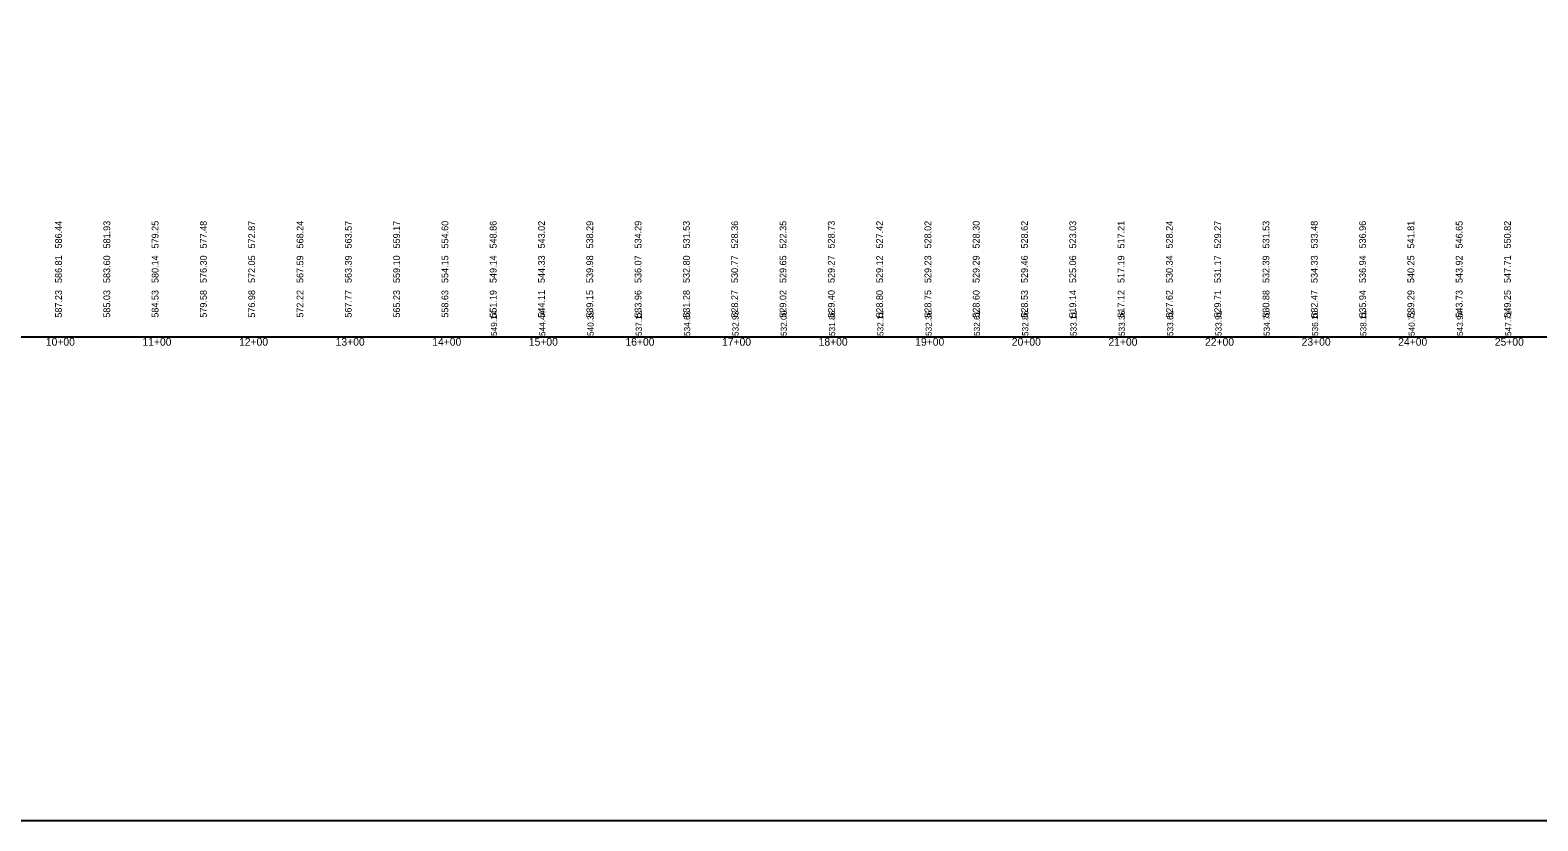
# Model space of a CAD drawing. Extents: x 1511486 to 1516886, y 901686 to 906985.
# Drawn here: x 1513041 to 1514602, y 903685 to 904504 of the extents above; entities that cross this region are included whole.
import ezdxf

# ---------------------------------------------------------------- set-up
doc = ezdxf.new("R2010")
doc.units = 0
for name, color, linetype in [('RD_DDB_StaTX', 7, 'Continuous'), ('RD_DDB_StripGrade', 7, 'Continuous'), ('RD_GPK_Profile_Cell', 7, 'Continuous'), ('RD_Sketch2', 7, 'Continuous'), ('RD_Sketch3', 7, 'Continuous')]:
    doc.layers.add(name, color=color, linetype=linetype)

msp = doc.modelspace()

# ---------------------------------------------------------------- linework, layer by layer
at = {"layer": 'RD_GPK_Profile_Cell'}
msp.add_line((1512074.7, 904186.4), (1516174.7, 904186.4), dxfattribs=at)
at = {"layer": 'RD_Sketch3'}
msp.add_lwpolyline([(1511486.2, 906985.3), (1516886.2, 906985.3), (1516886.2, 903685.3), (1511486.2, 903685.3)], close=True, dxfattribs=at)

# ---------------------------------------------------------------- texts
at = {"layer": 'RD_DDB_StaTX'}
for s, p in [('10+00', (1513057.1, 904177.4)), ('11+00', (1513157.1, 904177.4)), ('12+00', (1513257.1, 904177.4)), ('13+00', (1513357.1, 904177.4)), ('14+00', (1513457.1, 904177.4)), ('15+00', (1513557.1, 904177.4)), ('16+00', (1513657.1, 904177.4)), ('17+00', (1513757.1, 904177.4)), ('18+00', (1513857.1, 904177.4)), ('19+00', (1513957.1, 904177.4)), ('20+00', (1514057.1, 904177.4)), ('21+00', (1514157.1, 904177.4)), ('22+00', (1514257.1, 904177.4)), ('23+00', (1514357.1, 904177.4)), ('24+00', (1514457.1, 904177.4)), ('25+00', (1514557.1, 904177.4))]:
    msp.add_text(s, height=8, dxfattribs=at).set_placement(p)
at = {"layer": 'RD_DDB_StripGrade'}
for s, height, p in [('586.81', 7, (1513073.7, 904242.3)), ('583.60', 7, (1513123.7, 904242.3)), ('580.14', 7, (1513173.7, 904242.3)), ('576.30', 7, (1513223.7, 904242.3)), ('572.05', 7, (1513273.7, 904242.3)), ('567.59', 7, (1513323.7, 904242.3)), ('563.39', 7, (1513373.7, 904242.3)), ('559.10', 7, (1513423.7, 904242.3)), ('554.15', 7, (1513473.7, 904242.3)), ('549.14', 7, (1513523.7, 904242.3)), ('544.33', 7, (1513573.7, 904242.3)), ('539.98', 7, (1513623.7, 904242.3)), ('536.07', 7, (1513673.7, 904242.3)), ('532.80', 7, (1513723.7, 904242.3)), ('530.77', 7, (1513773.7, 904242.3)), ('529.65', 7, (1513823.7, 904242.3)), ('529.27', 7, (1513873.7, 904242.3)), ('529.12', 7, (1513923.7, 904242.3)), ('529.23', 7, (1513973.7, 904242.3)), ('529.29', 7, (1514023.7, 904242.3)), ('529.46', 7, (1514073.7, 904242.3)), ('525.06', 7, (1514123.7, 904242.3)), ('517.19', 7, (1514173.7, 904242.3)), ('530.34', 7, (1514223.7, 904242.3)), ('531.17', 7, (1514273.7, 904242.3)), ('532.39', 7, (1514323.7, 904242.3)), ('534.33', 7, (1514373.7, 904242.3)), ('536.94', 7, (1514423.7, 904242.3)), ('540.25', 7, (1514473.7, 904242.3)), ('543.92', 7, (1514523.7, 904242.3)), ('547.71', 7, (1514573.7, 904242.3)), ('549.14', 6.4, (1513524.2, 904187.4)), ('544.44', 6.4, (1513574.2, 904187.4)), ('540.39', 6.4, (1513624.2, 904187.4)), ('537.12', 6.4, (1513674.2, 904187.4)), ('534.63', 6.4, (1513724.2, 904187.4)), ('532.93', 6.4, (1513774.2, 904187.4)), ('532.00', 6.4, (1513824.2, 904187.4)), ('531.86', 6.4, (1513874.2, 904187.4)), ('532.11', 6.4, (1513924.2, 904187.4)), ('532.36', 6.4, (1513974.2, 904187.4)), ('532.61', 6.4, (1514024.2, 904187.4)), ('532.86', 6.4, (1514074.2, 904187.4)), ('533.11', 6.4, (1514124.2, 904187.4)), ('533.36', 6.4, (1514174.2, 904187.4)), ('533.61', 6.4, (1514224.2, 904187.4)), ('533.91', 6.4, (1514274.2, 904187.4)), ('534.70', 6.4, (1514324.2, 904187.4)), ('536.10', 6.4, (1514374.2, 904187.4)), ('538.11', 6.4, (1514424.2, 904187.4)), ('540.72', 6.4, (1514474.2, 904187.4)), ('543.94', 6.4, (1514524.2, 904187.4)), ('547.71', 6.4, (1514574.2, 904187.4))]:
    msp.add_text(s, height=height, rotation=90, dxfattribs=at).set_placement(p)
at = {"layer": 'RD_Sketch2'}
for s, p in [('586.44', (1513073.7, 904278.1)), ('581.93', (1513123.7, 904278.1)), ('579.25', (1513173.7, 904278.1)), ('577.48', (1513223.7, 904278.1)), ('572.87', (1513273.7, 904278.1)), ('568.24', (1513323.7, 904278.1)), ('563.57', (1513373.7, 904278.1)), ('559.17', (1513423.7, 904278.1)), ('554.60', (1513473.7, 904278.1)), ('548.86', (1513523.7, 904278.1)), ('543.02', (1513573.7, 904278.1)), ('538.29', (1513623.7, 904278.1)), ('534.29', (1513673.7, 904278.1)), ('531.53', (1513723.7, 904278.1)), ('528.36', (1513773.7, 904278.1)), ('522.35', (1513823.7, 904278.1)), ('528.73', (1513873.7, 904278.1)), ('527.42', (1513923.7, 904278.1)), ('528.02', (1513973.7, 904278.1)), ('528.30', (1514023.7, 904278.1)), ('528.62', (1514073.7, 904278.1)), ('523.03', (1514123.7, 904278.1)), ('517.21', (1514173.7, 904278.1)), ('528.24', (1514223.7, 904278.1)), ('529.27', (1514273.7, 904278.1)), ('531.53', (1514323.7, 904278.1)), ('533.48', (1514373.7, 904278.1)), ('536.96', (1514423.7, 904278.1)), ('541.81', (1514473.7, 904278.1)), ('546.65', (1514523.7, 904278.1)), ('550.82', (1514573.7, 904278.1)), ('587.23', (1513073.7, 904206.4)), ('585.03', (1513123.7, 904206.4)), ('584.53', (1513173.7, 904206.4)), ('579.58', (1513223.7, 904206.4)), ('576.98', (1513273.7, 904206.4)), ('572.22', (1513323.7, 904206.4)), ('567.77', (1513373.7, 904206.4)), ('565.23', (1513423.7, 904206.4)), ('558.63', (1513473.7, 904206.4)), ('551.19', (1513523.7, 904206.4)), ('544.11', (1513573.7, 904206.4)), ('539.15', (1513623.7, 904206.4)), ('533.96', (1513673.7, 904206.4)), ('531.28', (1513723.7, 904206.4)), ('528.27', (1513773.7, 904206.4)), ('529.02', (1513823.7, 904206.4)), ('529.40', (1513873.7, 904206.4)), ('528.80', (1513923.7, 904206.4)), ('528.75', (1513973.7, 904206.4)), ('528.60', (1514023.7, 904206.4)), ('528.53', (1514073.7, 904206.4)), ('519.14', (1514123.7, 904206.4)), ('517.12', (1514173.7, 904206.4)), ('527.62', (1514223.7, 904206.4)), ('529.71', (1514273.7, 904206.4)), ('530.88', (1514323.7, 904206.4)), ('532.47', (1514373.7, 904206.4)), ('535.94', (1514423.7, 904206.4)), ('539.29', (1514473.7, 904206.4)), ('543.73', (1514523.7, 904206.4)), ('549.25', (1514573.7, 904206.4))]:
    msp.add_text(s, height=7, rotation=90, dxfattribs=at).set_placement(p)

doc.saveas('drawing.dxf')
